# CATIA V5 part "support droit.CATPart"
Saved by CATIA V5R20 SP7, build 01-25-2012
Part number: support pied droit
Publications: "Corps principal", "Arête", "Face", "Face1"
Bounding box of the stored display mesh (mm): x 0.96 to 31.022, y -79 to 36, z -17.621 to 3.841
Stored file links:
  F:\Travaux\Modélisations\CFAO_2011\CFAO_2011_MMS\CFAO_2011_MMS_DONE\CFAO_2011_MMS_jboiteux\Catia\support droit.CATPart
  U:\finthinkmotion\stepper.CATProduct
  F:\Travaux\Modélisations\CFAO_2011\CFAO_2011_MMS\CFAO_2011_MMS_DONE\CFAO_2011_MMS_jboiteux\Catia\roulement1 pied droit.CATPart
  F:\Travaux\Modélisations\CFAO_2011\CFAO_2011_MMS\CFAO_2011_MMS_DONE\CFAO_2011_MMS_jboiteux\Catia\bati.CATPart
  F:\Travaux\Modélisations\CFAO_2011\CFAO_2011_MMS\CFAO_2011_MMS_DONE\CFAO_2011_MMS_jboiteux\Catia\entretoise pied droit.CATPart
  F:\Travaux\Modélisations\CFAO_2011\CFAO_2011_MMS\CFAO_2011_MMS_DONE\CFAO_2011_MMS_jboiteux\Catia\rondelle1 pied droit.CATPart
  F:\Travaux\Modélisations\CFAO_2011\CFAO_2011_MMS\CFAO_2011_MMS_DONE\CFAO_2011_MMS_jboiteux\Catia\support pied gauche.CATPart
  F:\Travaux\Modélisations\CFAO_2011\CFAO_2011_MMS\CFAO_2011_MMS_DONE\CFAO_2011_MMS_jboiteux\Catia\part3.CATPart
  F:\Travaux\Modélisations\CFAO_2011\CFAO_2011_MMS\CFAO_2011_MMS_DONE\CFAO_2011_MMS_jboiteux\Catia\Part1.CATPart
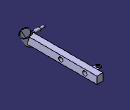
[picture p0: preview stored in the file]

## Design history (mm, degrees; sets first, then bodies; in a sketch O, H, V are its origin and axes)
Parameters
  rayontube = 9 mm {= External.royontubebati}
External parameters (linked from other documents)
  External.royontubebati = 9 mm
Set1
  DatumSurface1: linked copy from another document
  DatumSurface2: linked copy from another document
  Plane1: linked copy from another document
  Point1: linked copy from another document
  Plane2 to Plane4: linked copy from another document
  Point2: linked copy from another document
  Line1: linked copy from another document
  Line2: linked copy from another document
  Plane5: linked copy from another document
Body1 (main body)
  Sketch1 on face of DatumSurface1, origin (6.3878, 0, 11.0639), H (0, 1, 0), V (-0.866, 0, 0.5)
    projected circle E1 centre (-72, -21.4454) radius 7 from edge of DatumSurface1
    projected circle E2 centre (-72, -21.4454) radius 6 from edge of DatumSurface1
  Pad1: profile Sketch1, direction (0.5, 0, 0.866), up to face of DatumSurface2, offset -2
  Plane6: type OffsetPt, RefPlane Plane1, RefPoint Point1
  Sketch2 on Plane6, origin (0, -72, 0), H (-1, 0, 0), V (0, 0, 1)
    line L1 (-25.96, -0.321) -> (-16.96, -0.321)
    line L2 (-16.96, -0.321) -> (-16.96, -11.121)
    line L3 (-16.96, -11.121) -> (-25.96, -11.121)
    line L4 (-25.96, -11.121) -> (-25.96, -0.321)
    reference projected point E1 (-21.46, -5.721) from Point1
    reference projected point E2 (-21.46, -5.721) from Point1
    length L4 = 10.8 {= rayontube *1.2}
    length L3 = 9 {= rayontube}
    distance E1 L4 = 4.5 {= rayontube /2}
    distance E2 L3 = 5.4 {= rayontube*1.2 /2}
    horizontal: L1 H, L3 H
    vertical: L2 V, L4 V
  Pad2: profile Sketch2, direction (0, 1, 0), up to Plane2, opposite side length -4.5 {= -rayontube *1/2}
  Sketch3 on face of Pad2 from Sketch2.L2, origin (16.96, 0, 0), H (0, -1, 0), V (0, 0, 1)
    circle A1 centre (67.5, -0.321) radius 2.25
    point P1 (67.5, -0.321)
    reference projected point E1 (67.5, -0.321) from vertex [face of Pad2 from Sketch2.L1 | face of Pad2 from Sketch2.L2 | start face of Pad2]
    radius A1 = 2.25 {= rayontube /4}
    coincidence: E1 P1
  Pad3: profile Sketch3, direction (-1, 0, 0), length 9 {= rayontube}
  Sketch4 on end face of Pad3, origin (7.96, 0, 0), H (0, -1, 0), V (0, 0, 1)
    circle A1 centre (67.5, -0.321) radius 1.5
    point P1 (67.5, -0.321)
    reference projected circle E1 centre (67.5, -0.321) radius 2.25 from edge [face of Pad3 from Sketch3.A1 | end face of Pad3]
    radius A1 = 1.5 {= rayontube /6}
    concentricity: E1 P1
  Pad4: profile Sketch4, direction (-1, 0, 0), length 7 {= rayontube /9*7}
  Plane7: type OffsetPt, RefPlane Plane5, RefPoint Point2
  Sketch5 on Plane4, origin (0, 0, -5.7209), H (1, 0, 0), V (0, 1, 0)
    projected line E1 (16.96, -65.25) -> (16.96, 36) from edge [face of Pad2 from Sketch2.L1 | face of Pad2 from Sketch2.L2]
    arc A1 centre (11.46, 23) radius 3.6 from (10.906, 26.5571) to (10.906, 19.4429) ccw
    point P3 (11.46, 23)
    reference projected point E2 (11.46, 23) from Point2
    circle A2 centre (11.46, 23) radius 2.4324
    point P4 (11.46, 23)
    reference projected point E3 (11.46, 23) from Point2
    line L1 (10.906, 26.5571) -> (16.96, 27.5)
    point P6 (16.96, 27.5)
    line L2 (10.906, 19.4429) -> (16.96, 18.5)
    point P8 (16.96, 18.5)
    reference projected line E4 (11.46, 23) -> (21.46, 23) from Line1
    reference projected line E5 (11.46, 23) -> (21.46, 23) from Line1
    line L3 (16.96, 27.5) -> (16.96, 18.5)
    radius A1 = 3.6 {= rayontube /2.5}
    radius A2 = 2.4324 {= rayontube /3.7}
    distance E4 P6 = 4.5 {= rayontube /2}
    distance E5 P8 = 4.5 {= rayontube /2}
    coincidence: E2 P3, E3 P4, P6 E1, P8 E1
    tangency: A1 L1, L2 A1
    vertical: L3 V
  Pad5: profile Sketch5, direction (0, 0, 1), length 4.5 {= rayontube /2}, opposite side length -3.6 {= -rayontube/2.5}
  Sketch6 on Plane7, origin (0, 0, -5.7209), H (1, 0, 0), V (0, -1, 0)
    projected arc E1 centre (11.46, -23) radius 3.6 from (10.906, -19.4429) to (10.906, -26.5571) ccw from edge [start face of Pad5 | face of Pad5 from Sketch5.A1]
    projected line E2 (10.906, -19.4429) -> (16.96, -18.5) from edge [start face of Pad5 | face of Pad5 from Sketch5.L2]
    projected line E3 (16.96, -27.5) -> (16.96, -18.5) from edge [face of Pad2 from Sketch2.L2 | start face of Pad5]
    projected line E4 (16.96, -27.5) -> (10.906, -26.5571) from edge [start face of Pad5 | face of Pad5 from Sketch5.L1]
    projected circle E5 centre (11.46, -23) radius 2.4324 from edge [face of Pad5 from Sketch5.A2 | start face of Pad5]
  Pad6: profile Sketch6, direction (0, 0, -1), length 3.6 {= rayontube /2.5}, opposite side length -4.5 {= -rayontube /2}
  Sketch7 on end face of Pad1, origin (-1.9622, 0, -3.3987), H (0, -1, 0), V (-0.866, 0, 0.5)
    circle A1 centre (72, -21.4454) radius 6
    point P1 (72, -21.4454)
    reference projected point E1 (72, -21.4454) from Point1
    coincidence: E1 P1
  Pocket1: profile Sketch7, direction (0.5, 0, 0.866), through (limit type 6)
  Sketch8 on face of Pad2 from Sketch2.L4, origin (25.96, 0, 0), H (0, 1, 0), V (0, 0, 1)
    circle A1 centre (-18, -5.721) radius 3.15
    point P1 (-18, -5.721)
    circle A2 centre (18, -5.7209) radius 3.15
    point P2 (18, -5.7209)
    reference projected line E1 (36, -5.7209) -> (-72, -5.721) from Line2
    reference projected line E2 (36, -5.7209) -> (-72, -5.721) from Line2
    reference intersected line E3 through (36, 0) direction (0, -1) from Plane2
    radius A2 = 3.15 {= rayontube *7/20}
    distance P2 P1 = 36 {= rayontube *4}
    radius A1 = 3.15 {= rayontube *7/20}
    distance E3 P2 = 18 {= rayontube *2}
    coincidence: E1 P2, E2 P1
  Pocket2: profile Sketch8, direction (-1, 0, 0), length 4.5 {= rayontube /2}
  Sketch9 on end face of Pocket2, origin (21.46, 0, 0), H (0, 1, 0), V (0, 0, 1)
    circle A1 centre (-18, -5.721) radius 2.25
    point P1 (-18, -5.721)
    circle A2 centre (60.5197, 3.7713) radius 0
    circle A3 centre (18, -5.7209) radius 2.25
    point P2 (18, -5.7209)
    reference projected circle E1 centre (18, -5.7209) radius 3.15 from edge [face of Pad2 from Sketch2.L4 | face of Pocket2 from Sketch8.A2]
    reference projected circle E2 centre (-18, -5.721) radius 3.15 from edge [face of Pad2 from Sketch2.L4 | face of Pocket2 from Sketch8.A1]
    radius A3 = 2.25 {= rayontube /4}
    radius A1 = 2.25 {= rayontube /4}
    concentricity: E1 P2, E2 P1
  Pocket3: profile Sketch9, direction (1, 0, 0), through (limit type 6)
Relations
  Pad5.SecondLimit.Length = -rayontube /9*5 (deactivated)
